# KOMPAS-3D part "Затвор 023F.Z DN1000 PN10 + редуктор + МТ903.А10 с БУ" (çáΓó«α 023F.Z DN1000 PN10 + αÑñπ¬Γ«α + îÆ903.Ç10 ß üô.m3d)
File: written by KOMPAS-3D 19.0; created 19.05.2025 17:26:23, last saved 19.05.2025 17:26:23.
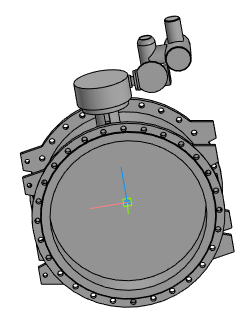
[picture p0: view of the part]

Document properties: Полное имя файла: Затвор 023F.Z DN1000 PN10 + редуктор + МТ903.А10 с БУ.a3d

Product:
- Part/product: Затвор 023F.Z DN1000 PN10 + редуктор + МТ903.А10 с БУ
    Масса: 1441.21

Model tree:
1. Операция без истории:1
